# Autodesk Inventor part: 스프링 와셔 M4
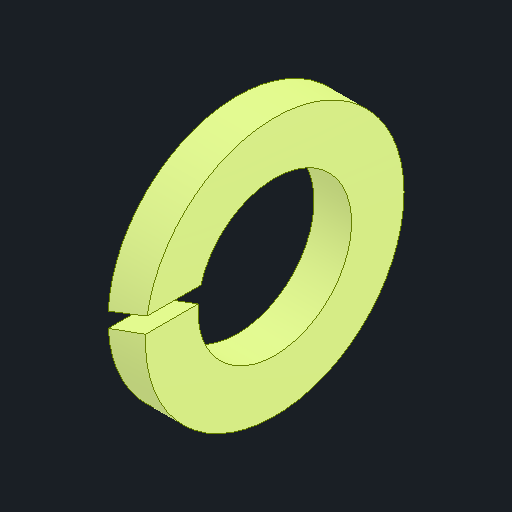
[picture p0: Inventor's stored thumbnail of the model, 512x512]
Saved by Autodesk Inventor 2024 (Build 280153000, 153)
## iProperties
Created: 2024-05
Part Number: 스프링 와셔 M4
Material: 강철, 연강
Description: 스프링 잠금 와셔
Document SubType Name: Modeling
Designer: kh_501
Density: 7.85 g/cm^3
Appearance: 기본값
Author: jhkim
Sending System: Autodesk Inventor 2025
Preprocessor: ST-DEVELOPER v20
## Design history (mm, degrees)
feature "Solid1"
node "솔리드1"
